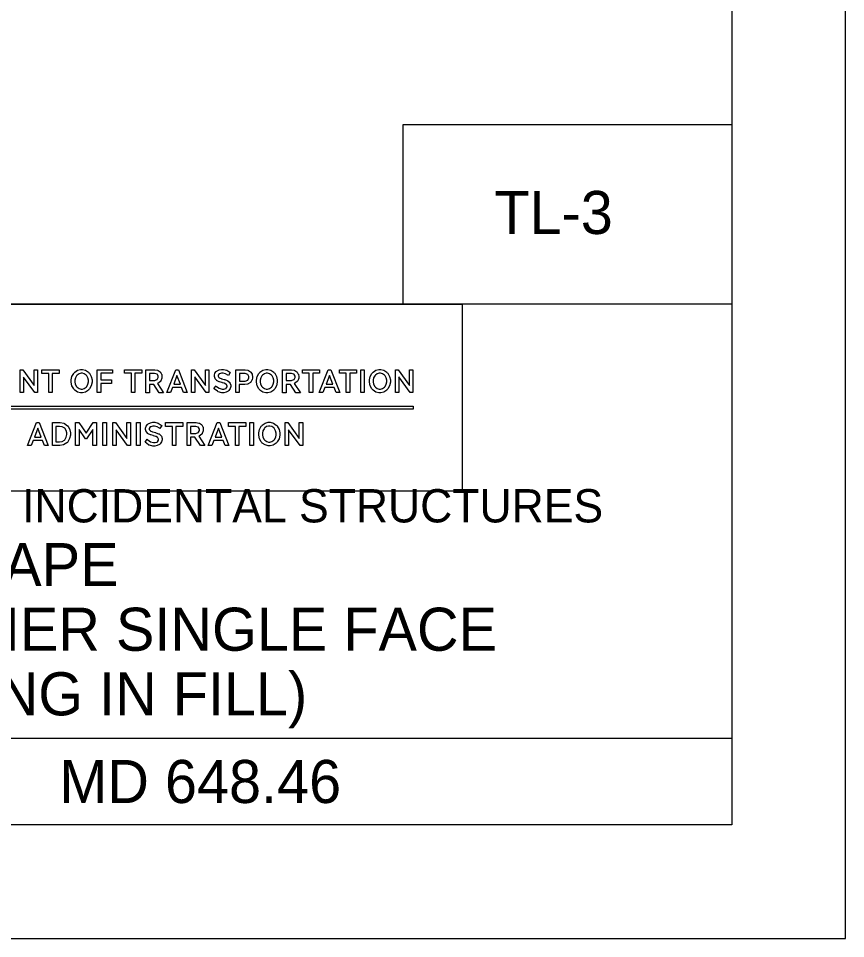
# Model space of a CAD drawing. Extents: x -32.9 to -15.8, y -6.5 to 4.5.
# Drawn here: x -18.128 to -15.824, y -6.497 to -3.933 of the extents above; entities that cross this region are included whole.
import ezdxf

# ---------------------------------------------------------------- set-up
doc = ezdxf.new("R2010")
doc.units = 0
for name, color, linetype in [('BORD-LINE', 7, 'Continuous'), ('Level 1', 7, 'Continuous'), ('Level 13', 7, 'Continuous'), ('MSHA-LOGO', 7, 'Continuous'), ('TTLB-TEXT', 7, 'Continuous'), ('USER-CLIP', 7, 'Continuous'), ('USER-LINE', 7, 'Continuous')]:
    doc.layers.add(name, color=color, linetype=linetype)

msp = doc.modelspace()

# ---------------------------------------------------------------- linework, layer by layer
at = {"layer": 'BORD-LINE'}
for p, q in [((-16.1409, -4.729), (-20.6138, -4.729)), ((-20.6138, -5.938), (-16.1409, -5.938))]:
    msp.add_line(p, q, dxfattribs=at)
msp.add_lwpolyline([(-23.5151, 4.1733), (-16.1409, 4.1733), (-16.1409, -6.1798), (-23.5151, -6.1798)], close=True, dxfattribs=at)
at = {"layer": 'Level 1'}
for p, q in [((-16.1409, -4.229), (-17.0575, -4.229)), ((-17.0575, -4.229), (-17.0575, -4.729))]:
    msp.add_line(p, q, dxfattribs=at)
at = {"layer": 'MSHA-LOGO'}
for points in [[(-18.0818, -4.9752), (-18.1132, -4.9318), (-18.1132, -4.9752), (-18.1227, -4.9752), (-18.1227, -4.9117), (-18.1152, -4.9117), (-18.0838, -4.9551), (-18.0838, -4.9117), (-18.0743, -4.9117), (-18.0743, -4.9752)], [(-18.0628, -4.9114), (-18.0147, -4.9114), (-18.0147, -4.9216), (-18.0337, -4.9216), (-18.0337, -4.9749), (-18.0435, -4.9749), (-18.0435, -4.9216), (-18.0625, -4.9216), (-18.0625, -4.9114)], [(-17.9725, -4.9202), (-17.9711, -4.9187), (-17.9632, -4.9131), (-17.9547, -4.9107), (-17.9519, -4.9107), (-17.9491, -4.9107), (-17.9406, -4.9129), (-17.9327, -4.9183), (-17.9313, -4.9199), (-17.9299, -4.9215), (-17.925, -4.9303), (-17.9228, -4.94), (-17.9228, -4.9433), (-17.9228, -4.9464), (-17.925, -4.956), (-17.9299, -4.9651), (-17.9313, -4.9666), (-17.9327, -4.9682), (-17.9406, -4.9736), (-17.9491, -4.9758), (-17.9519, -4.9758), (-17.9547, -4.9758), (-17.9632, -4.9736), (-17.9711, -4.9682), (-17.9725, -4.9666), (-17.9739, -4.9651), (-17.9789, -4.9562), (-17.981, -4.9465), (-17.981, -4.9433), (-17.981, -4.9401), (-17.9789, -4.9306), (-17.9739, -4.9218)], [(-17.965, -4.9591), (-17.9641, -4.9601), (-17.9589, -4.9638), (-17.9534, -4.9653), (-17.9516, -4.9653), (-17.9497, -4.9653), (-17.9443, -4.9638), (-17.9391, -4.9601), (-17.9381, -4.9591), (-17.9373, -4.9581), (-17.934, -4.9521), (-17.9326, -4.9455), (-17.9326, -4.9433), (-17.9326, -4.941), (-17.934, -4.9344), (-17.9373, -4.9285), (-17.9381, -4.9275), (-17.9391, -4.9264), (-17.9443, -4.9227), (-17.9497, -4.9212), (-17.9516, -4.9212), (-17.9534, -4.9212), (-17.9589, -4.9227), (-17.9641, -4.9264), (-17.965, -4.9275), (-17.9659, -4.9285), (-17.9691, -4.9344), (-17.9705, -4.941), (-17.9705, -4.9433), (-17.9705, -4.9455), (-17.9693, -4.9521), (-17.966, -4.9581)], [(-17.908, -4.9114), (-17.8662, -4.9114), (-17.8662, -4.9215), (-17.8982, -4.9215), (-17.8982, -4.9396), (-17.8685, -4.9396), (-17.8685, -4.9498), (-17.8982, -4.9498), (-17.8982, -4.9749), (-17.908, -4.9749)], [(-17.8325, -4.9114), (-17.7843, -4.9114), (-17.7843, -4.9215), (-17.8033, -4.9215), (-17.8033, -4.9749), (-17.8131, -4.9749), (-17.8131, -4.9215), (-17.8321, -4.9215), (-17.8321, -4.9114)], [(-17.7729, -4.9752), (-17.7729, -4.9117), (-17.7506, -4.9117), (-17.7479, -4.9117), (-17.7403, -4.9131), (-17.7395, -4.9133), (-17.7388, -4.9136), (-17.7331, -4.9174), (-17.7326, -4.9179), (-17.7322, -4.9184), (-17.7293, -4.9236), (-17.729, -4.9242), (-17.7288, -4.9248), (-17.7281, -4.93), (-17.7281, -4.9317), (-17.7281, -4.9346), (-17.7308, -4.9424), (-17.7313, -4.9433), (-17.7319, -4.9441), (-17.7395, -4.9498), (-17.7405, -4.9502), (-17.7235, -4.9755), (-17.7356, -4.9755), (-17.751, -4.9522), (-17.7631, -4.9522), (-17.7631, -4.9755), (-17.7729, -4.9755)], [(-17.7631, -4.9219), (-17.7631, -4.9413), (-17.7503, -4.9413), (-17.7481, -4.9413), (-17.7421, -4.9391), (-17.7415, -4.9387), (-17.741, -4.9383), (-17.7382, -4.9329), (-17.7382, -4.9311), (-17.7382, -4.9294), (-17.7407, -4.9246), (-17.7411, -4.9242), (-17.7416, -4.9238), (-17.7484, -4.9219), (-17.7506, -4.9219)], [(-17.6898, -4.9114), (-17.6822, -4.9114), (-17.6574, -4.9749), (-17.6678, -4.9749), (-17.6734, -4.9607), (-17.6989, -4.9607), (-17.7045, -4.9749), (-17.7146, -4.9749)], [(-17.605, -4.9752), (-17.6364, -4.9317), (-17.6364, -4.9752), (-17.6459, -4.9752), (-17.6459, -4.9117), (-17.6384, -4.9117), (-17.607, -4.9551), (-17.607, -4.9117), (-17.5975, -4.9117), (-17.5975, -4.9752)], [(-17.5487, -4.9528), (-17.5491, -4.9525), (-17.5532, -4.9498), (-17.5536, -4.9495), (-17.5541, -4.9493), (-17.5598, -4.9477), (-17.5605, -4.9475), (-17.5612, -4.9474), (-17.5674, -4.9455), (-17.568, -4.9452), (-17.5687, -4.945), (-17.5744, -4.9423), (-17.5749, -4.942), (-17.5754, -4.9416), (-17.5795, -4.9372), (-17.5798, -4.9367), (-17.5801, -4.9361), (-17.5818, -4.9304), (-17.5818, -4.9285), (-17.5818, -4.9267), (-17.5803, -4.9215), (-17.5766, -4.9165), (-17.5756, -4.9156), (-17.5745, -4.9147), (-17.5684, -4.9116), (-17.5618, -4.9104), (-17.5595, -4.9104), (-17.5564, -4.9104), (-17.547, -4.9126), (-17.5389, -4.918), (-17.5376, -4.9196), (-17.5428, -4.9275), (-17.5441, -4.9264), (-17.5507, -4.9226), (-17.5576, -4.9209), (-17.5598, -4.9209), (-17.562, -4.9209), (-17.5678, -4.9225), (-17.5684, -4.9229), (-17.5689, -4.9232), (-17.5716, -4.9271), (-17.5716, -4.9285), (-17.5716, -4.9297), (-17.5694, -4.9331), (-17.569, -4.9334), (-17.5686, -4.9337), (-17.5631, -4.9362), (-17.5625, -4.9364), (-17.5618, -4.9365), (-17.5547, -4.9384), (-17.5539, -4.9387), (-17.5532, -4.9389), (-17.5461, -4.9416), (-17.5454, -4.942), (-17.5448, -4.9423), (-17.5393, -4.9469), (-17.5389, -4.9475), (-17.5385, -4.9482), (-17.5363, -4.9546), (-17.5363, -4.9568), (-17.5363, -4.9586), (-17.5378, -4.9642), (-17.5414, -4.9693), (-17.5425, -4.9702), (-17.5436, -4.9711), (-17.5496, -4.9742), (-17.5558, -4.9755), (-17.5579, -4.9755), (-17.5615, -4.9755), (-17.5712, -4.9728), (-17.5723, -4.9722), (-17.5734, -4.9716), (-17.5824, -4.9648), (-17.5831, -4.964), (-17.5772, -4.9564), (-17.5759, -4.9579), (-17.5683, -4.9632), (-17.56, -4.9656), (-17.5572, -4.9656), (-17.5553, -4.9656), (-17.5498, -4.964), (-17.5494, -4.9637), (-17.5489, -4.9633), (-17.5464, -4.9594), (-17.5464, -4.9581), (-17.5465, -4.9575), (-17.5484, -4.9531)], [(-17.5225, -4.9752), (-17.5225, -4.9117), (-17.4996, -4.9117), (-17.4967, -4.9117), (-17.4887, -4.9131), (-17.4879, -4.9133), (-17.487, -4.9137), (-17.4811, -4.9178), (-17.4807, -4.9183), (-17.4803, -4.9187), (-17.4772, -4.9243), (-17.477, -4.9248), (-17.4769, -4.9254), (-17.4761, -4.9306), (-17.4761, -4.9324), (-17.4761, -4.9343), (-17.4771, -4.9394), (-17.4774, -4.94), (-17.4776, -4.9405), (-17.4809, -4.946), (-17.4813, -4.9465), (-17.4817, -4.947), (-17.488, -4.9512), (-17.4888, -4.9515), (-17.4897, -4.9518), (-17.4974, -4.9531), (-17.5, -4.9531), (-17.513, -4.9531), (-17.513, -4.9749), (-17.5225, -4.9749)], [(-17.5124, -4.9219), (-17.5124, -4.9433), (-17.4993, -4.9433), (-17.4967, -4.9433), (-17.489, -4.9405), (-17.4856, -4.9344), (-17.4856, -4.9324), (-17.4856, -4.9304), (-17.4888, -4.9245), (-17.4962, -4.9219), (-17.4987, -4.9219)], [(-17.4564, -4.9202), (-17.4551, -4.9187), (-17.4471, -4.9131), (-17.4386, -4.9107), (-17.4358, -4.9107), (-17.433, -4.9107), (-17.4245, -4.9129), (-17.4166, -4.9183), (-17.4152, -4.9199), (-17.4138, -4.9215), (-17.4089, -4.9303), (-17.4067, -4.94), (-17.4067, -4.9433), (-17.4067, -4.9464), (-17.4089, -4.956), (-17.4138, -4.9651), (-17.4152, -4.9666), (-17.4166, -4.9682), (-17.4245, -4.9736), (-17.433, -4.9758), (-17.4358, -4.9758), (-17.4386, -4.9758), (-17.4471, -4.9736), (-17.4551, -4.9682), (-17.4564, -4.9666), (-17.4578, -4.9651), (-17.4628, -4.9562), (-17.4649, -4.9465), (-17.4649, -4.9433), (-17.4649, -4.9409), (-17.4627, -4.9306), (-17.4578, -4.9218)], [(-17.4489, -4.9591), (-17.448, -4.9601), (-17.4428, -4.9638), (-17.4373, -4.9653), (-17.4355, -4.9653), (-17.4337, -4.9653), (-17.4282, -4.9638), (-17.423, -4.9601), (-17.4221, -4.9591), (-17.4212, -4.9581), (-17.418, -4.9521), (-17.4165, -4.9455), (-17.4165, -4.9433), (-17.4165, -4.941), (-17.418, -4.9344), (-17.4212, -4.9285), (-17.4221, -4.9275), (-17.423, -4.9264), (-17.4282, -4.9227), (-17.4337, -4.9212), (-17.4355, -4.9212), (-17.4373, -4.9212), (-17.4427, -4.9227), (-17.4479, -4.9264), (-17.4489, -4.9275), (-17.4498, -4.9285), (-17.453, -4.9344), (-17.4545, -4.941), (-17.4545, -4.9433), (-17.4545, -4.9455), (-17.4532, -4.9521), (-17.4499, -4.9581)], [(-17.392, -4.9752), (-17.392, -4.9117), (-17.3697, -4.9117), (-17.3669, -4.9117), (-17.3594, -4.9131), (-17.3586, -4.9133), (-17.3579, -4.9136), (-17.3521, -4.9174), (-17.3517, -4.9179), (-17.3513, -4.9184), (-17.3484, -4.9236), (-17.3481, -4.9242), (-17.348, -4.9248), (-17.3471, -4.93), (-17.3471, -4.9317), (-17.3471, -4.9346), (-17.3498, -4.9424), (-17.3504, -4.9433), (-17.351, -4.9441), (-17.3586, -4.9498), (-17.3596, -4.9502), (-17.3425, -4.9755), (-17.3547, -4.9755), (-17.37, -4.9522), (-17.3821, -4.9522), (-17.3821, -4.9755), (-17.392, -4.9755)], [(-17.3821, -4.9219), (-17.3821, -4.9413), (-17.3694, -4.9413), (-17.3672, -4.9413), (-17.3611, -4.9391), (-17.3605, -4.9387), (-17.3601, -4.9383), (-17.3573, -4.9329), (-17.3573, -4.9311), (-17.3573, -4.9294), (-17.3597, -4.9246), (-17.3602, -4.9242), (-17.3607, -4.9238), (-17.3675, -4.9219), (-17.3697, -4.9219)], [(-17.337, -4.9114), (-17.2889, -4.9114), (-17.2889, -4.9215), (-17.3079, -4.9215), (-17.3079, -4.9749), (-17.3177, -4.9749), (-17.3177, -4.9215), (-17.3367, -4.9215), (-17.3367, -4.9114)], [(-17.265, -4.9114), (-17.2575, -4.9114), (-17.2326, -4.9749), (-17.2431, -4.9749), (-17.2486, -4.9607), (-17.2745, -4.9607), (-17.28, -4.9749), (-17.2899, -4.9749)], [(-17.2339, -4.9114), (-17.1858, -4.9114), (-17.1858, -4.9215), (-17.2048, -4.9215), (-17.2048, -4.9749), (-17.2146, -4.9749), (-17.2146, -4.9215), (-17.2336, -4.9215), (-17.2336, -4.9114)], [(-17.1743, -4.9114), (-17.1645, -4.9114), (-17.1645, -4.9749), (-17.1743, -4.9749)], [(-17.1416, -4.9202), (-17.1402, -4.9187), (-17.1323, -4.9131), (-17.1238, -4.9107), (-17.121, -4.9107), (-17.1182, -4.9107), (-17.1097, -4.9129), (-17.1018, -4.9183), (-17.1004, -4.9199), (-17.099, -4.9215), (-17.0941, -4.9303), (-17.0919, -4.94), (-17.0919, -4.9433), (-17.0919, -4.9464), (-17.0941, -4.956), (-17.099, -4.9651), (-17.1004, -4.9666), (-17.1018, -4.9682), (-17.1097, -4.9736), (-17.1182, -4.9758), (-17.121, -4.9758), (-17.1238, -4.9758), (-17.1323, -4.9736), (-17.1402, -4.9682), (-17.1416, -4.9666), (-17.143, -4.9651), (-17.148, -4.9562), (-17.1501, -4.9465), (-17.1501, -4.9433), (-17.1501, -4.9401), (-17.1481, -4.9306), (-17.1431, -4.9218)], [(-17.1344, -4.9591), (-17.1335, -4.9601), (-17.1283, -4.9638), (-17.1229, -4.9653), (-17.121, -4.9653), (-17.1192, -4.9653), (-17.1137, -4.9638), (-17.1085, -4.9601), (-17.1076, -4.9591), (-17.1067, -4.9581), (-17.1034, -4.9521), (-17.102, -4.9455), (-17.102, -4.9433), (-17.102, -4.941), (-17.1034, -4.9344), (-17.1067, -4.9285), (-17.1076, -4.9275), (-17.1085, -4.9264), (-17.1137, -4.9227), (-17.1192, -4.9212), (-17.121, -4.9212), (-17.1228, -4.9212), (-17.1282, -4.9227), (-17.1334, -4.9264), (-17.1344, -4.9275), (-17.1353, -4.9285), (-17.1386, -4.9344), (-17.14, -4.941), (-17.14, -4.9433), (-17.14, -4.9455), (-17.1386, -4.9521), (-17.1353, -4.9581)], [(-17.0366, -4.9752), (-17.068, -4.9317), (-17.068, -4.9752), (-17.0775, -4.9752), (-17.0775, -4.9117), (-17.07, -4.9117), (-17.0385, -4.9551), (-17.0385, -4.9117), (-17.0291, -4.9117), (-17.0291, -4.9752)], [(-17.6953, -4.9515), (-17.6767, -4.9515), (-17.6862, -4.9275)], [(-17.2709, -4.9515), (-17.2522, -4.9515), (-17.2617, -4.9275)], [(-19.1447, -5.0131), (-17.028, -5.0131), (-17.028, -5.021), (-19.1447, -5.021)], [(-18.0774, -5.0587), (-18.0697, -5.0587), (-18.0445, -5.1229), (-18.055, -5.1229), (-18.0605, -5.1088), (-18.0867, -5.1088), (-18.0921, -5.1229), (-18.1023, -5.1229)], [(-18.0832, -5.0991), (-18.0643, -5.0991), (-18.0739, -5.0747)], [(-18.0333, -5.0587), (-18.0154, -5.0587), (-18.0117, -5.0587), (-18.0014, -5.0608), (-18.0004, -5.0612), (-17.9994, -5.0616), (-17.9908, -5.0675), (-17.9902, -5.0683), (-17.9895, -5.069), (-17.9851, -5.0773), (-17.9847, -5.0782), (-17.9844, -5.0792), (-17.9831, -5.0874), (-17.9831, -5.0901), (-17.9831, -5.0934), (-17.9853, -5.1033), (-17.9901, -5.1124), (-17.9915, -5.1139), (-17.9928, -5.1154), (-18.0019, -5.1207), (-18.0128, -5.1229), (-18.0164, -5.1229), (-18.0333, -5.1229)], [(-18.0234, -5.0693), (-18.0234, -5.1126), (-18.0157, -5.1126), (-18.0133, -5.1126), (-18.0058, -5.1111), (-17.9998, -5.1075), (-17.9988, -5.1065), (-17.9978, -5.1054), (-17.9947, -5.0993), (-17.9934, -5.0924), (-17.9934, -5.0901), (-17.9934, -5.0878), (-17.9948, -5.081), (-17.9989, -5.0745), (-18.0058, -5.0706), (-18.013, -5.0693), (-18.0154, -5.0693)], [(-17.9684, -5.0587), (-17.9595, -5.0587), (-17.9391, -5.0885), (-17.9192, -5.0587), (-17.9106, -5.0587), (-17.9106, -5.1229), (-17.9205, -5.1229), (-17.9205, -5.0782), (-17.9381, -5.1036), (-17.9407, -5.1036), (-17.9585, -5.0779), (-17.9585, -5.1226), (-17.9684, -5.1226)], [(-17.8927, -5.0587), (-17.8828, -5.0587), (-17.8828, -5.1229), (-17.8927, -5.1229)], [(-17.8237, -5.1229), (-17.8553, -5.0792), (-17.8553, -5.1229), (-17.8649, -5.1229), (-17.8649, -5.0587), (-17.8573, -5.0587), (-17.8256, -5.1027), (-17.8256, -5.0587), (-17.816, -5.0587), (-17.816, -5.1229)], [(-17.7985, -5.0587), (-17.7886, -5.0587), (-17.7886, -5.1229), (-17.7985, -5.1229)], [(-17.7397, -5.1007), (-17.74, -5.1004), (-17.7442, -5.0978), (-17.7448, -5.0975), (-17.7454, -5.0973), (-17.7512, -5.0954), (-17.7518, -5.0953), (-17.7525, -5.0951), (-17.7588, -5.0933), (-17.7595, -5.093), (-17.7601, -5.0928), (-17.766, -5.0901), (-17.7665, -5.0898), (-17.7671, -5.0895), (-17.7713, -5.0849), (-17.7716, -5.0844), (-17.772, -5.0838), (-17.7735, -5.0779), (-17.7735, -5.076), (-17.7735, -5.0742), (-17.7719, -5.069), (-17.7682, -5.064), (-17.7672, -5.0631), (-17.7661, -5.0623), (-17.76, -5.0592), (-17.7531, -5.058), (-17.7509, -5.058), (-17.7477, -5.058), (-17.7381, -5.0604), (-17.7299, -5.0658), (-17.7285, -5.0673), (-17.7339, -5.0754), (-17.7351, -5.0742), (-17.7418, -5.0703), (-17.7488, -5.0686), (-17.7512, -5.0686), (-17.7533, -5.0686), (-17.7593, -5.0702), (-17.7598, -5.0705), (-17.7604, -5.0709), (-17.7633, -5.075), (-17.7633, -5.0763), (-17.7633, -5.0776), (-17.7612, -5.0811), (-17.7608, -5.0815), (-17.7604, -5.0818), (-17.7548, -5.0842), (-17.7541, -5.0844), (-17.7533, -5.0845), (-17.7462, -5.0867), (-17.7454, -5.0869), (-17.7446, -5.0871), (-17.7375, -5.0899), (-17.7368, -5.0901), (-17.7362, -5.0904), (-17.7306, -5.0953), (-17.7301, -5.0959), (-17.7297, -5.0965), (-17.7275, -5.1031), (-17.7275, -5.1052), (-17.7275, -5.1071), (-17.7292, -5.1128), (-17.7329, -5.1181), (-17.7339, -5.119), (-17.735, -5.1199), (-17.741, -5.1231), (-17.7474, -5.1245), (-17.7496, -5.1245), (-17.7533, -5.1245), (-17.7631, -5.1218), (-17.7643, -5.1213), (-17.7655, -5.1207), (-17.7745, -5.1137), (-17.7751, -5.1129), (-17.7691, -5.1052), (-17.7678, -5.1067), (-17.7602, -5.1122), (-17.7515, -5.1145), (-17.7486, -5.1145), (-17.7466, -5.1145), (-17.7411, -5.1129), (-17.7406, -5.1126), (-17.7402, -5.1123), (-17.7378, -5.1082), (-17.7378, -5.1068), (-17.7378, -5.1053), (-17.7394, -5.101)], [(-17.7183, -5.0587), (-17.6697, -5.0587), (-17.6697, -5.0693), (-17.6889, -5.0693), (-17.6889, -5.1229), (-17.6988, -5.1229), (-17.6988, -5.0693), (-17.7179, -5.0693), (-17.7179, -5.0587)], [(-17.6582, -5.1229), (-17.6582, -5.0587), (-17.6355, -5.0587), (-17.6327, -5.0587), (-17.6251, -5.06), (-17.6243, -5.0603), (-17.6235, -5.0605), (-17.6177, -5.0643), (-17.6173, -5.0648), (-17.6169, -5.0652), (-17.614, -5.0706), (-17.6138, -5.0712), (-17.6136, -5.0717), (-17.6128, -5.0768), (-17.6128, -5.0786), (-17.6128, -5.0814), (-17.6158, -5.0893), (-17.6164, -5.0901), (-17.6169, -5.0909), (-17.6247, -5.0966), (-17.6256, -5.0969), (-17.6084, -5.1226), (-17.6205, -5.1226), (-17.6362, -5.0991), (-17.6483, -5.0991), (-17.6483, -5.1226), (-17.6582, -5.1226)], [(-17.6483, -5.0693), (-17.6483, -5.0888), (-17.6355, -5.0888), (-17.6333, -5.0888), (-17.6271, -5.0867), (-17.6266, -5.0863), (-17.626, -5.0858), (-17.6234, -5.0806), (-17.6234, -5.0789), (-17.6234, -5.0771), (-17.6258, -5.0722), (-17.6263, -5.0718), (-17.6267, -5.0714), (-17.6336, -5.0693), (-17.6358, -5.0693)], [(-17.5742, -5.0587), (-17.5665, -5.0587), (-17.5413, -5.1229), (-17.5518, -5.1229), (-17.5576, -5.1088), (-17.5837, -5.1088), (-17.5892, -5.1229), (-17.5994, -5.1229)], [(-17.5799, -5.0991), (-17.5611, -5.0991), (-17.5707, -5.0747)], [(-17.5429, -5.0587), (-17.4943, -5.0587), (-17.4943, -5.0693), (-17.5135, -5.0693), (-17.5135, -5.1229), (-17.5234, -5.1229), (-17.5234, -5.0693), (-17.5425, -5.0693), (-17.5425, -5.0587)], [(-17.4828, -5.0587), (-17.4729, -5.0587), (-17.4729, -5.1229), (-17.4828, -5.1229)], [(-17.4499, -5.0676), (-17.4485, -5.066), (-17.4404, -5.0604), (-17.4319, -5.058), (-17.4291, -5.058), (-17.4263, -5.058), (-17.4178, -5.0604), (-17.4097, -5.0658), (-17.4084, -5.0673), (-17.407, -5.0689), (-17.402, -5.0778), (-17.3997, -5.0875), (-17.3997, -5.0908), (-17.3997, -5.094), (-17.4019, -5.1036), (-17.4069, -5.1126), (-17.4084, -5.1142), (-17.4098, -5.1158), (-17.4179, -5.1213), (-17.4263, -5.1235), (-17.4291, -5.1235), (-17.432, -5.1235), (-17.4406, -5.1211), (-17.4485, -5.1157), (-17.4499, -5.1142), (-17.4513, -5.1127), (-17.4564, -5.1037), (-17.4585, -5.094), (-17.4585, -5.0908), (-17.4585, -5.0876), (-17.4564, -5.0781), (-17.4513, -5.0692)], [(-17.4425, -5.1068), (-17.4416, -5.1079), (-17.4363, -5.1114), (-17.4309, -5.1129), (-17.4291, -5.1129), (-17.4273, -5.1129), (-17.4217, -5.1114), (-17.4163, -5.1079), (-17.4154, -5.1068), (-17.4144, -5.1058), (-17.4112, -5.0998), (-17.41, -5.093), (-17.41, -5.0908), (-17.41, -5.0886), (-17.4114, -5.0819), (-17.4147, -5.0758), (-17.4157, -5.0747), (-17.4167, -5.0737), (-17.4219, -5.0701), (-17.4273, -5.0686), (-17.4291, -5.0686), (-17.431, -5.0686), (-17.4364, -5.0701), (-17.4417, -5.0737), (-17.4425, -5.0747), (-17.4434, -5.0758), (-17.4466, -5.0818), (-17.448, -5.0885), (-17.448, -5.0908), (-17.448, -5.093), (-17.4466, -5.0998), (-17.4434, -5.1058)], [(-17.3435, -5.1229), (-17.3751, -5.0792), (-17.3751, -5.1229), (-17.3847, -5.1229), (-17.3847, -5.0587), (-17.377, -5.0587), (-17.3454, -5.1027), (-17.3454, -5.0587), (-17.3358, -5.0587), (-17.3358, -5.1229)]]:
    msp.add_lwpolyline(points, close=True, dxfattribs=at)
at = {"layer": 'USER-CLIP'}
msp.add_lwpolyline([(-15.824, 4.5033), (-24.324, 4.5033), (-24.324, -6.4967), (-15.824, -6.4967)], close=True, dxfattribs=at)
at = {"layer": 'USER-LINE'}
msp.add_lwpolyline([(-16.8918, -5.2497), (-19.8629, -5.2497), (-19.8629, -4.729), (-16.8918, -4.729)], close=True, dxfattribs=at)

# ---------------------------------------------------------------- texts
at = {"layer": 'BORD-LINE'}
for p in [(-16.1409, -4.4946), (-16.1409, -4.729)]:
    msp.add_text('HDVBARREIRA', height=6e-12, rotation=180, dxfattribs=at).set_placement(p)
at = {"layer": 'Level 13'}
for s, p in [('34 INCH F SHAPE', (-19.1956, -5.5146)), ('CONCRETE TRAFFIC BARRIER SINGLE FACE', (-20.2815, -5.6946)), ('TYPE 2 (FREE STANDING IN FILL)', (-19.9006, -5.8746))]:
    msp.add_text(s, height=0.120019, dxfattribs=at).set_placement(p)
at = {"layer": 'TTLB-TEXT'}
for s, height, p in [('TL-3', 0.12, (-16.8022, -4.5333)), ('STANDARDS FOR HIGHWAYS AND INCIDENTAL STRUCTURES', 0.09269, (-20.218, -5.337)), ('MD 648.46', 0.12, (-18.0138, -6.1189))]:
    msp.add_text(s, height=height, dxfattribs=at).set_placement(p)

doc.saveas('drawing.dxf')
